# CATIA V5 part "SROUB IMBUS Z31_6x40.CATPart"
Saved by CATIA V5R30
Part number: SROUB IMBUS Z31/6x40
Bounding box of the stored display mesh (mm): x -6 to 40, y -4.99 to 4.99, z -5 to 5
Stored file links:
  C:\Users\ondra\Desktop\PŘÍLOHA P III\CATIA\SROUB IMBUS Z31_6x40.CATPart
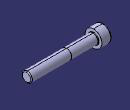
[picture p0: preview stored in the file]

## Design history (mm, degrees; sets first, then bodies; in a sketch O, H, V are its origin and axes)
Set1
  DatumSurface1 to DatumSurface29 "Z31/6x40"
  Join1: Elements (DatumSurface1; DatumSurface2; DatumSurface3; DatumSurface4; DatumSurface5; DatumSurface6; DatumSurface7; DatumSurface8; DatumSurface9; DatumSurface10; DatumSurface11; DatumSurface12; DatumSurface13; DatumSurface14; DatumSurface15; DatumSurface16; DatumSurface17; DatumSurface18; DatumSurface19; DatumSurface20; DatumSurface21; DatumSurface22; DatumSurface23; DatumSurface24; DatumSurface25; DatumSurface26; DatumSurface27; DatumSurface28; DatumSurface29)
Set2 "Geometry Failure"
  Set3 "FaceKO#Z31/6x40#409"
    DatumSurface30 "Sur409_1"
    Circle1 "Crv409_1": stored without definition
    DatumCurve1 "PCrv409_1"
    Circle2 "Crv409_2": stored without definition
    DatumCurve2 "PCrv409_2"
    Circle3 "Crv409_3": stored without definition
    DatumCurve3 "PCrv409_3"
    Circle4 "Crv409_4": stored without definition
    DatumCurve4 "PCrv409_4"
Body1 (main body)
  CloseSurface1: CloseElement Join1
